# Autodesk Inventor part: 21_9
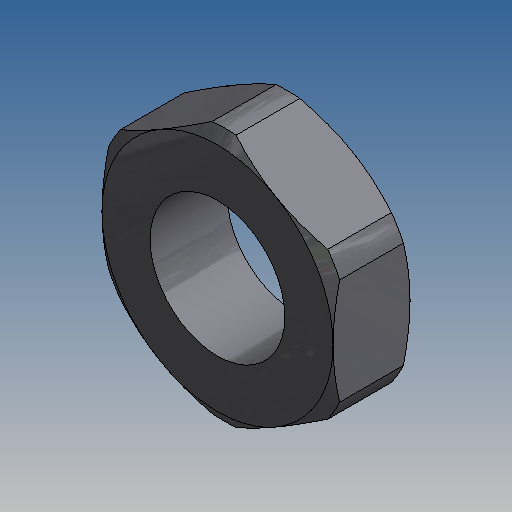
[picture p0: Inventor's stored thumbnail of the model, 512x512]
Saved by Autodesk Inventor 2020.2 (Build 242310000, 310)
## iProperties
Part Number: 21_9
Material: Generic
Document SubType Name: Modeling
Designer: amoles
Appearance: Default
Author: amoles
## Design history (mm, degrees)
feature "Base1"
body "Solid1"
